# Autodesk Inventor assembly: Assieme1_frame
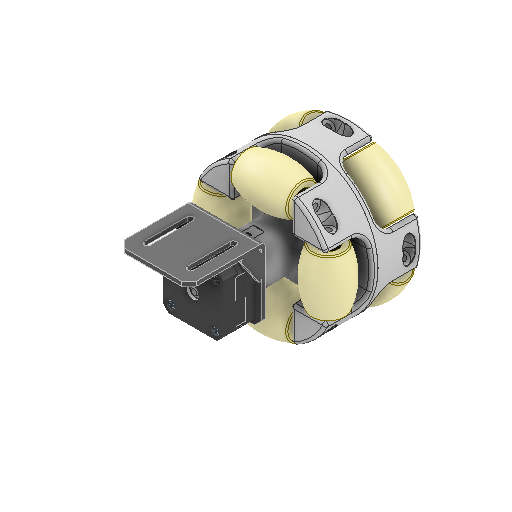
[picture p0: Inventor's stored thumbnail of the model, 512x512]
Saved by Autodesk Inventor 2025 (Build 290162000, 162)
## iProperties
Created: 2025-05
Part Number: Assieme1_frame
Document SubType Name: Assembly
Designer: R5800u
Author: R5800u
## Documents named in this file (8)
- C:\Users\R5800u\Desktop\mecanum7\Assieme1_frame.iam
- C:\Users\R5800u\Desktop\mecanum7\Parte1c.ipt
- C:\Users\R5800u\Desktop\mecanum7\Parte1a.ipt
- C:\Users\R5800u\Desktop\mecanum6\nema17_pancake.iam
- C:\Users\R5800u\Desktop\mecanum6\rullo.ipt
- C:\Users\R5800u\Documents\Inventor\Content Center Files\R2025\it-IT\AS 1112 (2)\AS 1112 - M4  Tipo 5.ipt
- C:\Users\R5800u\Documents\Inventor\Content Center Files\R2025\it-IT\AS 1421(2)\AS 1421 - M4 x 16 Punta a coppa.ipt
- C:\Users\R5800u\Desktop\mecanum6\NEMA 17 A-Body.ipt
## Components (14 placed, 7 different names)
1. Parte1c:1 — Coincidente:1, Coincidente:2, Angolo:1, Coincidente:6, Coincidente:7
2. Parte1a:1 — Coincidente:1, Coincidente:2, Angolo:1, Rotazionale:1, Angolo:2, Coincidente:3, Coincidente:4, Angolo:3
3. nema17_pancake:1 [sub-assembly] — Rotazionale:1, Angolo:2, Rotazionale:2, Angolo:4
4. AS 1112 (2) - Metrico M4  Tipo 5:1 — Angolo:3
5. AS 1421 Punta a coppa - Metrico M4 x 16 Punta a coppa:1
6. NEMA 17 A-Body:1 — Rotazionale:2, Angolo:4
7. rullo:1 — Coincidente:3, Coincidente:4
8. rullo:2
9. rullo:3
10. rullo:4
11. rullo:5 — Coincidente:6, Coincidente:7
12. rullo:6
13. rullo:7
14. rullo:8
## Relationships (12: Mate 6, Angle 4, RevoluteJoint 2)
- Coincidente:1 [Mate]: Parte1c:1 ↔ Parte1a:1
- Coincidente:2 [Mate]: Parte1c:1 ↔ Parte1a:1
- Angolo:1 [Angle]: Parte1c:1 ↔ Parte1a:1
- Rotazionale:1 [RevoluteJoint]: Parte1a:1 ↔ nema17_pancake:1
- Angolo:2 [Angle]: Parte1a:1 ↔ nema17_pancake:1
- Coincidente:3 [Mate]: Parte1a:1 ↔ rullo:1
- Coincidente:4 [Mate]: Parte1a:1 ↔ rullo:1
- Angolo:3 [Angle]: Parte1a:1 ↔ AS 1112 (2) - Metrico M4  Tipo 5:1
- Rotazionale:2 [RevoluteJoint]: nema17_pancake:1 ↔ NEMA 17 A-Body:1
- Angolo:4 [Angle]: nema17_pancake:1 ↔ NEMA 17 A-Body:1
- Coincidente:6 [Mate]: Parte1c:1 ↔ rullo:5
- Coincidente:7 [Mate]: Parte1c:1 ↔ rullo:5
